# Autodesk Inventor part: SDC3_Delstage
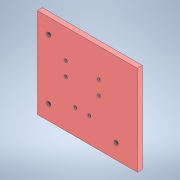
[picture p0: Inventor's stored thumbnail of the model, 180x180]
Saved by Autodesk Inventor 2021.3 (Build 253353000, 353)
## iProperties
Created: 2022-01
Part Number: SDC3_Delstage
Material: 一般
Document SubType Name: Modeling
Designer: kengo
Density: 1 g/cm^3
Appearance: 既定
Author: kengo
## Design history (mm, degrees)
sketch "スケッチ1"
  geometry: L1 (-82.158, 126.906)-(117.842, 126.906); L2 (117.842, 126.906)-(117.842, -53.094); L3 (117.842, -53.094)-(-82.158, -53.094); L4 (-82.158, -53.094)-(-82.158, 126.906); 1 further point
  constraints: 8 end point, 2 parallel, 1 horizontal, 1 perpendicular
  dimensions: "d0" = 200 distance of L1.start L1.end; "d1" = 180 distance of L1.end L2.end
extrude "押し出し1" new body sketch "スケッチ1" distance "d2" = 10; taper "d3" = 0 deg
sketch "スケッチ2"
  geometry: L1 (82.158, 126.906)-(82.158, -53.094) reference; L2 (-117.842, -53.094)-(-117.842, 126.906) reference; L3 (-117.842, 126.906)-(82.158, 126.906) reference; L4 (82.158, -53.094)-(-117.842, -53.094) reference; 7 further points
  dimensions: "d4" = 57 distance from line of L1 point (25.158, 40.906); "d5" = 57 distance from line of L1 point (25.158, 68.906); "d6" = 77 distance from line of L2 point (-40.842, 40.906); "d7" = 77 distance from line of L2 point (-40.842, 68.906); "d8" = 28 distance of point (-40.842, 68.906) point (-40.842, 40.906); "d9" = 28 distance of point (25.158, 40.906) point (25.158, 68.906); "d10" = 58 distance from line of L3 point (25.158, 68.906); "d11" = 58 distance from line of L3 point (-40.842, 68.906); "d12" = 76 distance from line of L1 point (6.158, -2.811); "d13" = 28 distance of point (-21.84, -3.094) point (6.158, -2.811); "d14" = 50 distance from line of L4 point (-21.84, -3.094)
hole "穴1" sketch "スケッチ2" at (25.158, 40.906), (25.158, 68.906), (-40.842, 40.906), (-40.842, 68.906), (6.158, -2.811), (-21.84, -3.094) diameter "d15" = 6; stored, may be unused: countersink angle "d19" = 90 deg, drill point angle "d21" = 118 deg; dims "d16" = 40, "d17" = 4, "d18" = 2, "d20" = 51.2
sketch "スケッチ3"
  geometry: L1 (-82.158, 126.906)-(-82.158, -53.094) reference; L2 (117.842, 126.906)-(-82.158, 126.906) reference; L3 (117.842, -53.094)-(117.842, 126.906) reference; L4 (-82.158, 126.906)-(-82.158, -53.094) reference; 4 further points
  dimensions: "d22" = 22.5 distance from line of L1 point (-59.658, -23.094); "d23" = 150 distance from line of L2 point (-59.658, -23.094); "d24" = 150 distance from line of L2 point (75.342, -23.094); "d25" = 42.5 distance from line of L3 point (75.342, -23.094); "d33" = 22.5 distance from line of L4 point (-59.658, 96.906); "d34" = 120 distance of point (-59.658, 96.906) point (-59.658, -23.094)
hole "穴2" sketch "スケッチ3" at (-59.658, -23.094), (75.342, -23.094), (-59.658, 96.906) diameter "d26" = 8; stored, may be unused: countersink angle "d30" = 90 deg, drill point angle "d32" = 0 deg; dims "d27" = 10, "d28" = 4, "d29" = 2, "d31" = 8
node "ソリッド1"
